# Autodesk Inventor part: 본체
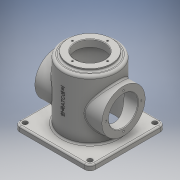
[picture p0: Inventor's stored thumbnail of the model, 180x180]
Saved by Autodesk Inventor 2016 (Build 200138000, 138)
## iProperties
Created: 2019-08
Part Number: 본체
Material: 일반
Document SubType Name: Modeling
Designer: user
Density: 1 g/cm^3
Appearance: 기본값
Author: user
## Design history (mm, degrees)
sketch "스케치1"
  geometry: L1 (-60, -70)-(60, -70); L2 (70, -60)-(70, 60); L3 (60, 70)-(-60, 70); L4 (-70, 60)-(-70, -60); L5 (-70, -70)-(70, 70); L6 (70, -70)-(-70, 70); A1 r 10 centre (-60, 60) between (-60, 70) and (-70, 60); A2 r 10 centre (60, 60) between (70, 60) and (60, 70); A3 r 10 centre (60, -60) between (60, -70) and (70, -60); A4 r 10 centre (-60, -60) between (-70, -60) and (-60, -70); 1 further point
  constraints: 12 end point, 8 point on circle, 8 point on line, 8 tangent, 4 centre point, 3 equal radius, 2 midpoint, 2 parallel, 1 horizontal, 1 perpendicular
  dimensions: "d0" = 140 distance of L5.end L6.end; "d1" = 140 distance of L6.start L5.end; "d2" = 10 radius of A1
extrude "돌출1" new body sketch "스케치1" distance "d3" = 10; taper "d4" = 0 deg
node "작업 평면1"
sketch "스케치8"
  geometry: C1 r 50 at (0, 0); 1 further point
  constraints: 1 centre point, 1 coincident
  dimensions: "d28" = 100 diameter of C1
extrude "돌출6" join sketch "스케치8" distance "d29" = 110; taper "d30" = 0 deg
node "작업 평면3"
sketch "스케치10"
  geometry: C1 r 40 at (0, 0); 1 further point
  constraints: 1 centre point, 1 coincident
  dimensions: "d32" = 80 diameter of C1
extrude "돌출7" join sketch "스케치10" stored distance "d33" = 110; taper "d34" = 0 deg
sketch "스케치11"
  geometry: L1 (-60, 70)-(60, 70) reference; L2 (70, 60)-(70, -60) reference; L3 (60, -70)-(-60, -70) reference; L4 (-70, -60)-(-70, 60) reference; C1 r 50 at (0, 0) reference; A1 r 10 centre (-60, 60) between (-60, 70) and (-70, 60) reference; A2 r 10 centre (60, 60) between (70, 60) and (60, 70) reference; A3 r 10 centre (60, -60) between (60, -70) and (70, -60) reference; A4 r 10 centre (-60, -60) between (-70, -60) and (-60, -70) reference; 5 further points
  constraints: 4 coincident
hole "구멍2" sketch "스케치11" at (-60, 60), (60, 60), (60, -60), (-60, -60) diameter "d35" = 9; stored, may be unused: countersink angle "d39" = 90 deg, drill point angle "d41" = 118 deg; dims "d36" = 6, "d37" = 4, "d38" = 2, "d40" = 8
node "작업 평면4"
sketch "스케치12"
  geometry: L1 (-60, 0)-(60, 0) reference; C1 r 40 at (0, 60); 2 further points
  constraints: 1 centre point, 1 midpoint, 1 vertical alignment
  dimensions: "d43" = 80 diameter of C1; "d44" = 60 distance from line of L1 C1.centre
extrude "돌출8" join sketch "스케치12" distance "d45" = 124; taper "d46" = 0 deg
sketch "스케치13"
  geometry: C1 r 45 at (0, 0); 1 further point
  constraints: 1 centre point, 1 coincident
  dimensions: "d47" = 90 diameter of C1
extrude "돌출9" cut sketch "스케치13" distance "d48" = 112; taper "d49" = 0 deg
sketch "스케치14"
  geometry: 2 further points
  constraints: 1 coincident
hole "구멍3" sketch "스케치14" at (0, 0) diameter "d50" = 54; stored, may be unused: countersink angle "d54" = 90 deg, drill point angle "d56" = 118 deg; dims "d51" = 6, "d52" = 4, "d53" = 2, "d55" = 8
sketch "스케치15"
  geometry: C1 r 40 at (0, 0) reference; 2 further points
  constraints: 1 coincident
hole "구멍4" sketch "스케치15" at (0, 0) diameter "d57" = 54; stored, may be unused: countersink angle "d61" = 90 deg, drill point angle "d63" = 118 deg; dims "d58" = 6, "d59" = 4, "d60" = 2, "d62" = 8
sketch "스케치16" dims "d64" = 65
  geometry: C1 r 27 at (0, 0) reference; 3 further points
  constraints: 2 vertical alignment, 1 coincident, 2 other
hole "구멍5" sketch "스케치16" at (0, -32.5) diameter "d65" = 3.242; stored, may be unused: countersink angle "d69" = 90 deg, drill point angle "d71" = 118 deg; dims "d66" = 8, "d67" = 4, "d68" = 2, "d70" = 10
sketch "스케치17" dims "d75" = 65
  geometry: 3 further points
  constraints: 2 vertical alignment, 1 coincident, 2 other
hole "구멍6" sketch "스케치17" at (0, 32.5) diameter "d76" = 3.242; stored, may be unused: countersink angle "d80" = 90 deg, drill point angle "d82" = 118 deg; dims "d77" = 8, "d78" = 4, "d79" = 2, "d81" = 10
chamfer "모따기1" distance "d86" = 1; stored, may be unused: second distance "d87" = 2, angle "d88" = 45 deg
fillet "모깎기1" dims "d89" = 3
fillet "모깎기2" dims "d90" = 3
fillet "모깎기3" dims "d91" = 3
fillet "모깎기4" dims "d92" = 3
fillet "모깎기5" dims "d93" = 3
chamfer "모따기2" distance "d94" = 1; stored, may be unused: second distance "d95" = 2, angle "d96" = 45 deg
node "작업 평면5"
sketch "스케치18" dims "d0" = 140, "d1" = 140, "d2" = 10
  geometry: L1 (-60, 0)-(60, 0) reference; 3 further points
  constraints: 1 midpoint, 1 vertical alignment, 1 other
  dimensions: "d98" = 70 distance from line of L1 point (0, 70)
feature "엠보싱1" sketch "스케치18" dims "d0" = 140, "d1" = 140, "d2" = 10, "d99" = 0.5, "d100" = 0
fillet "모깎기6" dims "d101" = 5
node "솔리드1"
pattern_circular "원형 패턴1" dims angle "d73" = 360 deg
mirror "대칭2"
pattern_circular "원형 패턴2" dims angle "d84" = 360 deg
node "투영된 루프1"
node "절단 모서리 투영2"
other parameters: "d31" = -125, "d42" = 62, "d97" = -71.25
